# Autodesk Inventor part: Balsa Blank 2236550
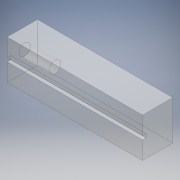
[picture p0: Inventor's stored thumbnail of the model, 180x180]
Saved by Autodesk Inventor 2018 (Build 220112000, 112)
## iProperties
Created: 2015-05
Part Number: Balsa Blank 2236550
Material: Generic
Document SubType Name: Modeling
Designer: Brett
Density: 1 g/cm^3
Appearance: Polycarbonate - Clear
Author: Brett
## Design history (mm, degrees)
sketch "Sketch1"
  geometry: L1 (0, 21)-(223, 21); L2 (223, 21)-(223, -29); L3 (223, -29)-(0, -29); L4 (0, -29)-(0, 21); 1 further point
  constraints: 8 end point, 2 parallel, 1 horizontal, 1 perpendicular
  dimensions: "d0" = 223 distance of L2.end L3.end; "d1" = 50 distance of L1.end L2.end; "d2" = 21 distance from line of point (0, 0) L1
extrude "Extrusion1" new body sketch "Sketch1" stored distance "d3" = 65; taper "d4" = 0 deg
sketch "Sketch2"
  geometry: L1 (-29, 32.5)-(-29, -32.5) reference; L2 (-29, 3)-(-23, 3); L3 (-23, 3)-(-23, -3); L4 (-23, -3)-(-29, -3); L5 (-29, -3)-(-29, 3); 1 further point
  constraints: 8 end point, 2 parallel, 1 horizontal, 1 perpendicular, 1 point on line
  dimensions: "d5" = 6 distance of L3.end L4.end; "d6" = 6 distance of L2.end L3.end; "d7" = 3 distance from line of point (0, 0) L4
extrude "Extrusion2" cut sketch "Sketch2" extent not by distance; stored distance "d8" = 32.5; taper "d9" = 0 deg
hole "Hole1" diameter "d12" = 19; stored, may be unused: countersink angle "d16" = 90 deg, drill point angle "d18" = 0 deg; dims "d10" = 32.5, "d11" = 21, "d13" = 6, "d14" = 4, "d15" = 2, "d17" = 50
node "Safety Plane"
node "Bottom Plane"
body "Solid1"
other parameters: "d19" = 35.5, "d20" = -3
